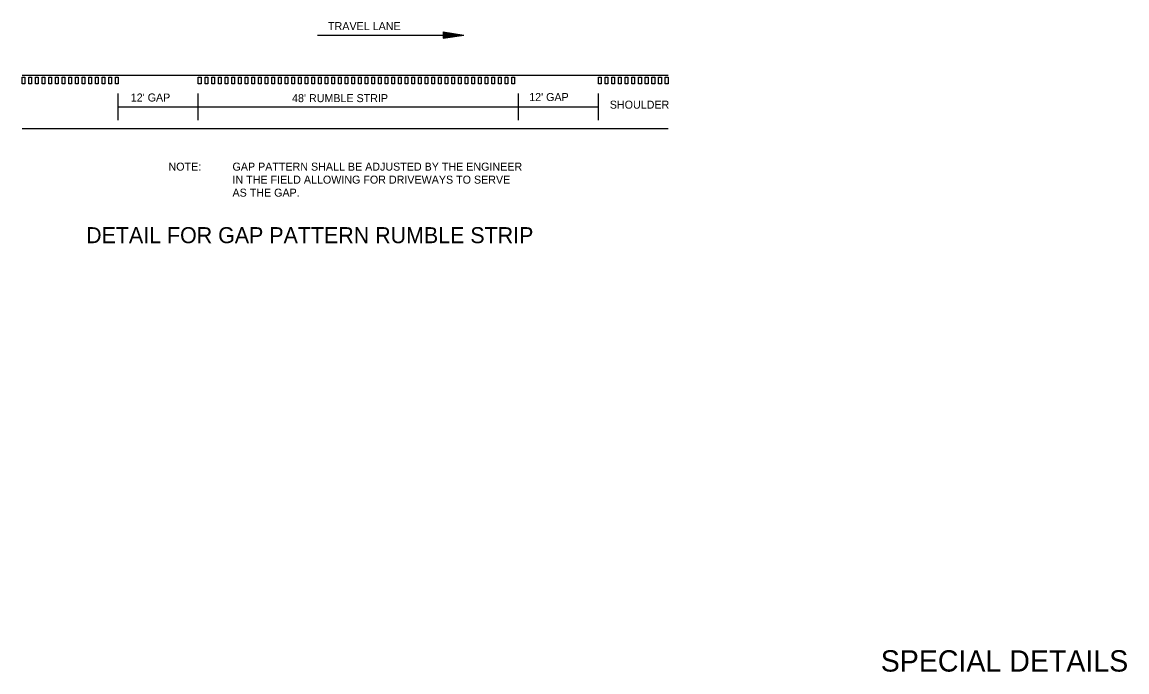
# Model space of a CAD drawing. Extents: x 1929624 to 1935547, y 596315 to 605721.
# Drawn here: x 1933651 to 1934272, y 600380 to 600745 of the extents above; entities that cross this region are included whole.
import ezdxf

# ---------------------------------------------------------------- set-up
doc = ezdxf.new("R2010")
doc.units = 0
for name, color, linetype in [('R_Annotation', 7, 'Continuous'), ('R_Dimension', 7, 'Continuous'), ('R_Draft', 7, 'Continuous')]:
    doc.layers.add(name, color=color, linetype=linetype)

msp = doc.modelspace()

# ---------------------------------------------------------------- linework, layer by layer
at = {"layer": 'R_Dimension'}
for p, q in [((1933887.28, 600739.68), (1933898.89, 600737.94)), ((1933887.28, 600739.68), (1933887.28, 600736.2)), ((1933887.28, 600739.39), (1933896.95, 600737.94)), ((1933887.28, 600739.1), (1933894.95, 600737.94)), ((1933887.28, 600738.81), (1933893.02, 600737.94)), ((1933887.28, 600738.5), (1933891.05, 600737.94)), ((1933887.28, 600738.21), (1933889.11, 600737.94)), ((1933887.28, 600736.2), (1933898.89, 600737.94)), ((1933887.28, 600737.37), (1933891.05, 600737.94)), ((1933887.28, 600736.78), (1933894.95, 600737.94)), ((1933887.28, 600736.49), (1933896.95, 600737.94)), ((1933887.28, 600737.08), (1933893.02, 600737.94)), ((1933887.28, 600737.67), (1933889.11, 600737.94))]:
    msp.add_line(p, q, dxfattribs=at)
at = {"layer": 'R_Draft'}
for p, q in [((1933816.75, 600737.94), (1933898.89, 600737.94)), ((1933650.62, 600715.44), (1934013.76, 600715.44)), ((1933704.68, 600690.04), (1933704.68, 600705.04)), ((1933749.69, 600690.04), (1933749.69, 600705.04)), ((1933929.69, 600690.04), (1933929.69, 600705.04)), ((1933974.69, 600690.04), (1933974.69, 600705.04)), ((1933704.68, 600697.54), (1933749.69, 600697.54)), ((1933749.69, 600697.54), (1933929.69, 600697.54)), ((1933929.69, 600697.54), (1933974.69, 600697.54)), ((1933650.62, 600685.44), (1934013.76, 600685.44))]:
    msp.add_line(p, q, dxfattribs=at)
for points in [[(1933650.62, 600710.44), (1933650.62, 600714.19), (1933652.18, 600714.19), (1933652.18, 600710.44), (1933650.62, 600710.44)], [(1933654.37, 600710.44), (1933654.37, 600714.19), (1933655.93, 600714.19), (1933655.93, 600710.44), (1933654.37, 600710.44)], [(1933658.12, 600710.44), (1933658.12, 600714.19), (1933659.68, 600714.19), (1933659.68, 600710.44), (1933658.12, 600710.44)], [(1933661.87, 600710.44), (1933661.87, 600714.19), (1933663.43, 600714.19), (1933663.43, 600710.44), (1933661.87, 600710.44)], [(1933665.62, 600710.44), (1933665.62, 600714.19), (1933667.18, 600714.19), (1933667.18, 600710.44), (1933665.62, 600710.44)], [(1933669.37, 600710.44), (1933669.37, 600714.19), (1933670.93, 600714.19), (1933670.93, 600710.44), (1933669.37, 600710.44)], [(1933673.12, 600710.44), (1933673.12, 600714.19), (1933674.68, 600714.19), (1933674.68, 600710.44), (1933673.12, 600710.44)], [(1933676.87, 600710.44), (1933676.87, 600714.19), (1933678.43, 600714.19), (1933678.43, 600710.44), (1933676.87, 600710.44)], [(1933680.62, 600710.44), (1933680.62, 600714.19), (1933682.18, 600714.19), (1933682.18, 600710.44), (1933680.62, 600710.44)], [(1933684.37, 600710.44), (1933684.37, 600714.19), (1933685.93, 600714.19), (1933685.93, 600710.44), (1933684.37, 600710.44)], [(1933688.12, 600710.44), (1933688.12, 600714.19), (1933689.68, 600714.19), (1933689.68, 600710.44), (1933688.12, 600710.44)], [(1933691.87, 600710.44), (1933691.87, 600714.19), (1933693.43, 600714.19), (1933693.43, 600710.44), (1933691.87, 600710.44)], [(1933695.62, 600710.44), (1933695.62, 600714.19), (1933697.18, 600714.19), (1933697.18, 600710.44), (1933695.62, 600710.44)], [(1933699.37, 600710.44), (1933699.37, 600714.19), (1933700.93, 600714.19), (1933700.93, 600710.44), (1933699.37, 600710.44)], [(1933703.12, 600710.44), (1933703.12, 600714.19), (1933704.68, 600714.19), (1933704.68, 600710.44), (1933703.12, 600710.44)], [(1933749.7, 600710.44), (1933749.7, 600714.19), (1933751.26, 600714.19), (1933751.26, 600710.44), (1933749.7, 600710.44)], [(1933753.45, 600710.44), (1933753.45, 600714.19), (1933755.01, 600714.19), (1933755.01, 600710.44), (1933753.45, 600710.44)], [(1933757.2, 600710.44), (1933757.2, 600714.19), (1933758.76, 600714.19), (1933758.76, 600710.44), (1933757.2, 600710.44)], [(1933760.95, 600710.44), (1933760.95, 600714.19), (1933762.51, 600714.19), (1933762.51, 600710.44), (1933760.95, 600710.44)], [(1933764.7, 600710.44), (1933764.7, 600714.19), (1933766.26, 600714.19), (1933766.26, 600710.44), (1933764.7, 600710.44)], [(1933768.45, 600710.44), (1933768.45, 600714.19), (1933770.01, 600714.19), (1933770.01, 600710.44), (1933768.45, 600710.44)], [(1933772.2, 600710.44), (1933772.2, 600714.19), (1933773.76, 600714.19), (1933773.76, 600710.44), (1933772.2, 600710.44)], [(1933775.95, 600710.44), (1933775.95, 600714.19), (1933777.51, 600714.19), (1933777.51, 600710.44), (1933775.95, 600710.44)], [(1933779.7, 600710.44), (1933779.7, 600714.19), (1933781.26, 600714.19), (1933781.26, 600710.44), (1933779.7, 600710.44)], [(1933783.45, 600710.44), (1933783.45, 600714.19), (1933785.01, 600714.19), (1933785.01, 600710.44), (1933783.45, 600710.44)], [(1933787.2, 600710.44), (1933787.2, 600714.19), (1933788.76, 600714.19), (1933788.76, 600710.44), (1933787.2, 600710.44)], [(1933790.95, 600710.44), (1933790.95, 600714.19), (1933792.51, 600714.19), (1933792.51, 600710.44), (1933790.95, 600710.44)], [(1933794.7, 600710.44), (1933794.7, 600714.19), (1933796.26, 600714.19), (1933796.26, 600710.44), (1933794.7, 600710.44)], [(1933798.45, 600710.44), (1933798.45, 600714.19), (1933800.01, 600714.19), (1933800.01, 600710.44), (1933798.45, 600710.44)], [(1933802.2, 600710.44), (1933802.2, 600714.19), (1933803.76, 600714.19), (1933803.76, 600710.44), (1933802.2, 600710.44)], [(1933805.95, 600710.44), (1933805.95, 600714.19), (1933807.51, 600714.19), (1933807.51, 600710.44), (1933805.95, 600710.44)], [(1933809.7, 600710.44), (1933809.7, 600714.19), (1933811.26, 600714.19), (1933811.26, 600710.44), (1933809.7, 600710.44)], [(1933813.45, 600710.44), (1933813.45, 600714.19), (1933815.01, 600714.19), (1933815.01, 600710.44), (1933813.45, 600710.44)], [(1933817.2, 600710.44), (1933817.2, 600714.19), (1933818.76, 600714.19), (1933818.76, 600710.44), (1933817.2, 600710.44)], [(1933820.95, 600710.44), (1933820.95, 600714.19), (1933822.51, 600714.19), (1933822.51, 600710.44), (1933820.95, 600710.44)], [(1933824.7, 600710.44), (1933824.7, 600714.19), (1933826.26, 600714.19), (1933826.26, 600710.44), (1933824.7, 600710.44)], [(1933828.45, 600710.44), (1933828.45, 600714.19), (1933830.01, 600714.19), (1933830.01, 600710.44), (1933828.45, 600710.44)], [(1933832.2, 600710.44), (1933832.2, 600714.19), (1933833.76, 600714.19), (1933833.76, 600710.44), (1933832.2, 600710.44)], [(1933835.95, 600710.44), (1933835.95, 600714.19), (1933837.51, 600714.19), (1933837.51, 600710.44), (1933835.95, 600710.44)], [(1933839.7, 600710.44), (1933839.7, 600714.19), (1933841.26, 600714.19), (1933841.26, 600710.44), (1933839.7, 600710.44)], [(1933843.45, 600710.44), (1933843.45, 600714.19), (1933845.01, 600714.19), (1933845.01, 600710.44), (1933843.45, 600710.44)], [(1933847.2, 600710.44), (1933847.2, 600714.19), (1933848.76, 600714.19), (1933848.76, 600710.44), (1933847.2, 600710.44)], [(1933850.95, 600710.44), (1933850.95, 600714.19), (1933852.51, 600714.19), (1933852.51, 600710.44), (1933850.95, 600710.44)], [(1933854.7, 600710.44), (1933854.7, 600714.19), (1933856.26, 600714.19), (1933856.26, 600710.44), (1933854.7, 600710.44)], [(1933858.45, 600710.44), (1933858.45, 600714.19), (1933860.01, 600714.19), (1933860.01, 600710.44), (1933858.45, 600710.44)], [(1933862.2, 600710.44), (1933862.2, 600714.19), (1933863.76, 600714.19), (1933863.76, 600710.44), (1933862.2, 600710.44)], [(1933865.95, 600710.44), (1933865.95, 600714.19), (1933867.51, 600714.19), (1933867.51, 600710.44), (1933865.95, 600710.44)], [(1933869.7, 600710.44), (1933869.7, 600714.19), (1933871.26, 600714.19), (1933871.26, 600710.44), (1933869.7, 600710.44)], [(1933873.45, 600710.44), (1933873.45, 600714.19), (1933875.01, 600714.19), (1933875.01, 600710.44), (1933873.45, 600710.44)], [(1933877.2, 600710.44), (1933877.2, 600714.19), (1933878.76, 600714.19), (1933878.76, 600710.44), (1933877.2, 600710.44)], [(1933880.95, 600710.44), (1933880.95, 600714.19), (1933882.51, 600714.19), (1933882.51, 600710.44), (1933880.95, 600710.44)], [(1933884.7, 600710.44), (1933884.7, 600714.19), (1933886.26, 600714.19), (1933886.26, 600710.44), (1933884.7, 600710.44)], [(1933888.45, 600710.44), (1933888.45, 600714.19), (1933890.01, 600714.19), (1933890.01, 600710.44), (1933888.45, 600710.44)], [(1933892.2, 600710.44), (1933892.2, 600714.19), (1933893.76, 600714.19), (1933893.76, 600710.44), (1933892.2, 600710.44)], [(1933895.95, 600710.44), (1933895.95, 600714.19), (1933897.52, 600714.19), (1933897.52, 600710.44), (1933895.95, 600710.44)], [(1933899.7, 600710.44), (1933899.7, 600714.19), (1933901.27, 600714.19), (1933901.27, 600710.44), (1933899.7, 600710.44)], [(1933903.45, 600710.44), (1933903.45, 600714.19), (1933905.02, 600714.19), (1933905.02, 600710.44), (1933903.45, 600710.44)], [(1933907.2, 600710.44), (1933907.2, 600714.19), (1933908.77, 600714.19), (1933908.77, 600710.44), (1933907.2, 600710.44)], [(1933910.95, 600710.44), (1933910.95, 600714.19), (1933912.52, 600714.19), (1933912.52, 600710.44), (1933910.95, 600710.44)], [(1933914.7, 600710.44), (1933914.7, 600714.19), (1933916.27, 600714.19), (1933916.27, 600710.44), (1933914.7, 600710.44)], [(1933918.45, 600710.44), (1933918.45, 600714.19), (1933920.02, 600714.19), (1933920.02, 600710.44), (1933918.45, 600710.44)], [(1933922.2, 600710.44), (1933922.2, 600714.19), (1933923.77, 600714.19), (1933923.77, 600710.44), (1933922.2, 600710.44)], [(1933925.95, 600710.44), (1933925.95, 600714.19), (1933927.52, 600714.19), (1933927.52, 600710.44), (1933925.95, 600710.44)], [(1933974.69, 600710.44), (1933974.69, 600714.19), (1933976.25, 600714.19), (1933976.25, 600710.44), (1933974.69, 600710.44)], [(1933978.44, 600710.44), (1933978.44, 600714.19), (1933980, 600714.19), (1933980, 600710.44), (1933978.44, 600710.44)], [(1933982.19, 600710.44), (1933982.19, 600714.19), (1933983.75, 600714.19), (1933983.75, 600710.44), (1933982.19, 600710.44)], [(1933985.94, 600710.44), (1933985.94, 600714.19), (1933987.5, 600714.19), (1933987.5, 600710.44), (1933985.94, 600710.44)], [(1933989.69, 600710.44), (1933989.69, 600714.19), (1933991.25, 600714.19), (1933991.25, 600710.44), (1933989.69, 600710.44)], [(1933993.44, 600710.44), (1933993.44, 600714.19), (1933995, 600714.19), (1933995, 600710.44), (1933993.44, 600710.44)], [(1933997.19, 600710.44), (1933997.19, 600714.19), (1933998.76, 600714.19), (1933998.76, 600710.44), (1933997.19, 600710.44)], [(1934000.94, 600710.44), (1934000.94, 600714.19), (1934002.51, 600714.19), (1934002.51, 600710.44), (1934000.94, 600710.44)], [(1934004.69, 600710.44), (1934004.69, 600714.19), (1934006.26, 600714.19), (1934006.26, 600710.44), (1934004.69, 600710.44)], [(1934008.44, 600710.44), (1934008.44, 600714.19), (1934010.01, 600714.19), (1934010.01, 600710.44), (1934008.44, 600710.44)], [(1934012.19, 600710.44), (1934012.19, 600714.19), (1934013.76, 600714.19), (1934013.76, 600710.44), (1934012.19, 600710.44)]]:
    msp.add_lwpolyline(points, dxfattribs=at)

# ---------------------------------------------------------------- texts
at = {"layer": 'R_Annotation'}
msp.add_text('SPECIAL DETAILS', height=12, rotation=360, dxfattribs=at).set_placement((1934133.35, 600380.15))
at = {"layer": 'R_Draft'}
for s, height, p in [('TRAVEL LANE', 4.5001, (1933822.63, 600740.71)), ("12' GAP", 4.5, (1933711.7, 600700.58)), ("48' RUMBLE STRIP", 4.5001, (1933802.39, 600700.23)), ("12' GAP", 4.5, (1933935.71, 600700.84)), ('SHOULDER', 4.5, (1933981.03, 600696.56)), ('NOTE:', 4.5, (1933732.91, 600661.72)), ('GAP PATTERN SHALL BE ADJUSTED BY THE ENGINEER', 4.5001, (1933768.91, 600661.72)), ('IN THE FIELD ALLOWING FOR DRIVEWAYS TO SERVE', 4.5001, (1933768.91, 600654.41)), ('AS THE GAP.', 4.5001, (1933768.91, 600647.1)), ('DETAIL FOR GAP PATTERN RUMBLE STRIP', 9.0002, (1933686.61, 600620.95))]:
    msp.add_text(s, height=height, dxfattribs=at).set_placement(p)

doc.saveas('drawing.dxf')
